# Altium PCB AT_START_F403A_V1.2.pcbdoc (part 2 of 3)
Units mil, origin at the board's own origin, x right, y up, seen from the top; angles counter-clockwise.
Board outline 5262.73 x 3522.74 mil, 2 copper layers (Top Layer, Bottom Layer); 135 components, 162 nets, 647 pads, 293 vias.
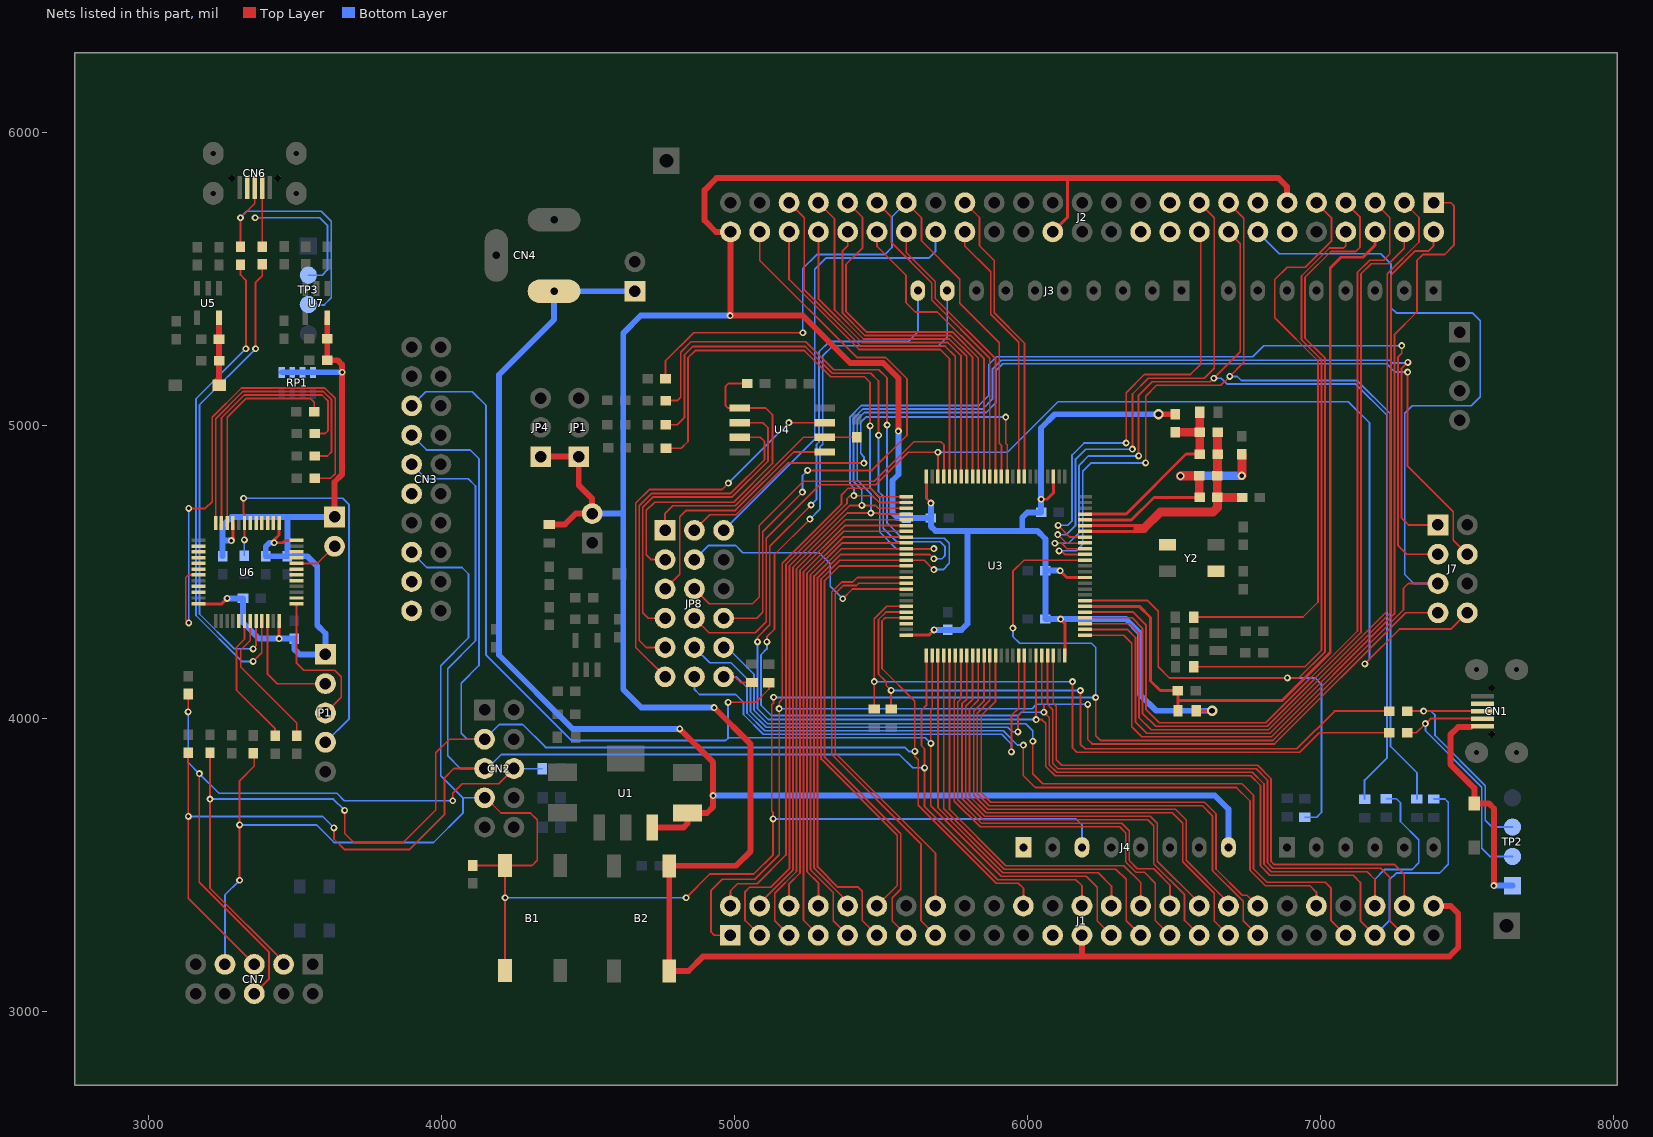
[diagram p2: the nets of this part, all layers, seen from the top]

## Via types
v1: diameter 23.62, hole 11.81, Top Layer to Bottom Layer, 286 vias
v2: diameter 28, hole 16, Top Layer to Bottom Layer, 3 vias
v3: diameter 35, hole 20, Top Layer to Bottom Layer, 2 vias
v4: diameter 29.53, hole 13.78, Top Layer to Bottom Layer, 1 vias
v5: diameter 31.5, hole 15.75, Top Layer to Bottom Layer, 1 vias

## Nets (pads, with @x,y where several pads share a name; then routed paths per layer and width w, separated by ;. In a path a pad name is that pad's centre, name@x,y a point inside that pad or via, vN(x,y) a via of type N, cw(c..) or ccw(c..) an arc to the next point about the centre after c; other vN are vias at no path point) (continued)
JDI: CN3.5 J1.27 R36.2 U3.77 | length 4479.2
  Top Layer w6: v1(4978.99,4056.68) 5072.99,4056.68 5118.45,4102.13 R36.2@5118.45,4123.59 ; U3.77@5675.49,4216.94 5675.49,4033.06 5670.99,4028.55 v1(5670.99,3916.74) 5670.99,3703.83 5911.73,3463.09 6201.64,3463.09 6238.99,3425.74 6238.99,3310.15 J1.27@6287.12,3262.02
  Bottom Layer w6: CN3.5@3898.99,5068.74 3946.99,5116.74 4105.99,5116.74 4152.99,5069.74 4152.99,4217.71 4443.96,3926.74 4971.37,3926.74 4978.99,3934.36 4978.99,3935.06 ; v1(4978.99,4056.68) 4978.99,3935.06 ; v1(5670.99,3916.74) 5651.85,3935.88 4979.82,3935.88 4978.99,3935.06
JTCK: CN2.5 CN3.9 CN7.5 J1.26 R41.1 U3.76 | length 6221.8
  Top Layer w6: R41.1@3136.85,3884.34 v1(3136.85,3667.34) 3136.85,3387.34 CN7.5@3361.85,3162.34 ; v1(3633.85,3628.34) 3633.85,3590.34 3670.13,3554.06 3891.37,3554.06 4011.37,3674.06 4011.37,3799.54 4042.57,3830.74 CN2.5@4147.99,3830.74 ; v1@5648.99,3833.06 5648.99,3701.78 5899.68,3451.09 6165.99,3451.09 6187.12,3429.96 J1.26@6187.12,3362.02 ; v1(5649.37,3833.06) 5649.37,3898.06 5638.87,3908.56 5638.87,4029.11 5655.81,4046.06 U3.76@5655.81,4216.94
  Bottom Layer w6: v1(3136.85,3667.34) 3594.85,3667.34 v1(3633.85,3628.34) ; CN3.9@3898.99,4868.74 3947.99,4819.74 4091.99,4819.74 4116.99,4794.74 4116.99,4266.74 4021.99,4171.74 4021.99,3873.74 4064.99,3830.74 CN2.5@4147.99,3830.74 4156.37,3830.74 4204.37,3878.74 4234.37,3878.74 5506.05,3878.74 5563.37,3878.74 5609.05,3833.06 v1(5649.37,3833.06)
JTMS: CN2.3 CN3.7 CN7.3 J1.22 R44.1 U3.72 | length 6275.2
  Top Layer w6: R44.1@3210.85,3884.34 3210.85,3422.55 3461.85,3171.55 CN7.3@3461.85,3162.34 ; v1(3670.37,3688.06) 3670.37,3608.95 3701.26,3578.06 3870.37,3578.06 3981.37,3689.06 3981.37,3884.06 4028.05,3930.74 CN2.3@4147.99,3930.74 ; U3.72@5586.91,4344.89 5515.06,4344.89 5504.37,4334.2 5504.37,4172.06 5616.37,4060.06 v1(5616.37,3889.06) 5616.37,3872.87 5628.18,3861.06 5628.18,3705.62 5894.71,3439.09 5969.64,3439.09 5987.12,3421.61 J1.22@5987.12,3362.02
  Bottom Layer w6: v1(3210.76,3726.42) 3632,3726.42 v1(3670.37,3688.06) ; CN3.7@3898.99,4968.74 3949.99,4917.74 4098.99,4917.74 4128.99,4887.74 4128.99,4182.74 4067.99,4121.74 4067.99,3951.74 4088.99,3930.74 CN2.3@4147.99,3930.74 4198.31,3981.06 4277.68,3981.06 4355.99,3902.74 5582.37,3902.74 5596.05,3889.06 v1(5616.37,3889.06)
LD1: LD1.2 U6.10 | length 723.1
  Top Layer w6: U6.10@3269.42,4668.34 3269.42,5029.75 3333.01,5093.34 3554.85,5093.34 3566.85,5081.34 LD1.2@3566.85,5048.34
LD2: LD2.2 U6.11 | length 914.2
  Top Layer w6: U6.11@3249.74,4668.34 3249.74,5027.04 3328.04,5105.34 3592.85,5105.34 3613.85,5084.34 3613.85,4984.34 3603.75,4974.24 LD2.2@3567.81,4974.24
LD3: LD3.2 U6.12 | length 1043.7
  Top Layer w6: U6.12@3230.05,4668.34 3230.05,5024.32 3323.07,5117.34 3597.82,5117.34 3625.85,5089.31 3625.85,4911.34 3611.85,4897.34 LD3.2@3567.85,4897.34
LD4: LD4.2 U6.19 | length 1781.6
  Top Layer w6: v1(3138.37,4328.06) 3128.37,4338.06 3128.37,4482.69 3136.86,4491.17 U6.19@3171,4491.17 ; v1(3138.37,4718.34) 3194.85,4718.34 3218.05,4741.55 3218.05,5029.29 3318.1,5129.34 3602.79,5129.34 3637.85,5094.28 3637.85,4837.34 3621.85,4821.34 LD4.2@3567.81,4821.34
  Bottom Layer w6: v1(3138.37,4328.06) v1(3138.37,4718.34)
M-ATLK_RX: R48.2 U6.31 | length 483.9
  Top Layer w6: U6.31@3348.16,4333.69 3348.16,4267.66 3315.85,4235.34 3315.85,4177.06 3506.85,3986.06 R48.2@3506.85,3942.34
M-ATLK_TX: R47.2 U6.30 | length 457.3
  Top Layer w6: U6.30@3328.48,4333.69 3328.48,4271.97 3301.11,4244.6 3301.11,4097.96 3432.85,3966.22 R47.2@3432.85,3942.34
M-BOOT0: J9.2 U6.44 | length 154.6
  Top Layer w6: U6.44@3505.64,4530.55 3577.05,4530.55 J9.2@3635.85,4589.34
M-NRST: C22.1 P1.4 U6.7 | length 1411.3
  Top Layer w6: v1(3325.37,4753.06) 3325.37,4702.33 3328.48,4699.22 U6.7@3328.48,4668.54 3328.48,4611.78 v1(3328.04,4611.34)
  Bottom Layer w6: v1(3325.37,4753.06) 3663.81,4753.06 3685.44,4731.43 3685.44,4000.93 P1.4@3604.85,3920.34 ; C22.1@3327.35,4556.67 v1@3327.35,4611.34
M-SWCLK: P1.3 U6.37 | length 520.5
  Top Layer w6: U6.37@3505.64,4392.75 3505.64,4191.24 3530.55,4166.34 3636.85,4166.34 3658.85,4144.34 3658.85,4074.34 P1.3@3604.85,4020.34
M-SWDIO: P1.2 U6.34 | length 392.1
  Top Layer w6: U6.34@3407.22,4333.89 3407.22,4152.97 3439.85,4120.34 P1.2@3604.85,4120.34
M-USB_DM: R38.2 U6.32 | length 1612.4
  Top Layer w6: v1(3357.85,4239.34) 3367.85,4249.34 U6.32@3367.85,4333.69 ; v1(3366.43,5263.34) 3366.43,5489.92 3388.85,5512.34 R38.2@3388.85,5551.19
  Bottom Layer w6: v1(3357.85,4239.34) 3293.56,4239.34 3174.85,4358.06 3174.85,5071.76 v1(3366.43,5263.34)
M-USB_DP: R37.2 U6.33 | length 1685.3
  Top Layer w6: R37.2@3314.85,5550.23 3314.85,5515.34 3333.43,5496.76 v1(3333.43,5263.34) ; v1(3357.85,4196.34) 3387.53,4226.03 U6.33@3387.53,4333.89
  Bottom Layer w6: v1(3333.43,5263.34) 3162.85,5092.76 3162.85,4353.08 3319.59,4196.34 v1(3357.85,4196.34)
NRST: B1.1 CB1.1 CN2.7 CN3.15 CN7.7 J2.14 J4.3 J7.5 R46.1 U3.14 | length 12191.6
  Top Layer w6: v1(3311.85,3449.34) v1(3311.85,3638.34) 3311.85,3789.34 3361.85,3839.34 3361.85,3879.34 R46.1@3358.85,3882.34 ; CB1.1@4106.99,3499.74 B1.1@4217.99,3499.74 ; CN2.7@4147.99,3730.74 4152.37,3730.74 4204.05,3679.06 4304.37,3679.06 4327.37,3656.06 4327.37,3517.06 4310.05,3499.74 B1.1@4217.99,3499.74 ; B1.1@4217.99,3140.74 v1(4217.99,3389.74) B1.1@4217.99,3499.74 ; v1(4835.99,3389.74) 4916.99,3470.74 5066.75,3470.74 5132.56,3536.55 v1(5132.56,3658.55) 5132.56,3680.06 5128.21,3684.4 5128.21,4048.9 5134.37,4055.06 v1(5134.37,4074.06) ; v1(5951.09,4309.74) 5951.09,4503.83 5988.99,4541.74 U3.14@6206.99,4541.74 ; v1(6233.37,4073.06) 6233.37,3942.06 6248.68,3926.74 6838.96,3926.74 ; 6838.67,3927.03 7274.69,4363.04 7283.96,4372.32 7283.96,4445.71 7300.42,4462.17 J7.5@7401.7,4462.17
  Bottom Layer w6: CN7.7@3261.85,3162.34 3261.85,3399.34 v1(3311.85,3449.34) ; v1(3311.85,3638.34) 3574.11,3638.34 3634.4,3578.06 3973.4,3578.06 4073.83,3678.49 4073.83,3730.74 ; CN3.15@3898.99,4568.74 3950.99,4516.74 4070.99,4516.74 4092.99,4494.74 4092.99,4276.68 3997.99,4181.68 3997.99,3806.58 4073.83,3730.74 ; CN2.7@4147.99,3730.74 4073.83,3730.74 ; v1(4217.99,3389.74) v1(4835.99,3389.74) ; v1(5132.56,3658.55) 6166.18,3658.55 6186.69,3638.04 J4.3@6186.69,3561.59 ; v1(5134.37,4074.06) 5135.37,4073.06 v1(6233.37,4073.06) 6233.37,4243.74 6219.05,4258.06 5974.37,4258.06 5951.09,4281.34 v1(5951.09,4309.74) ; J2.14@6786.7,5661.59 6860.55,5587.74 7206.99,5587.74 7240.99,5553.74 7240.99,5403.74 7258.99,5385.74 7518.99,5385.74 7545.99,5358.74 7545.99,5099.74 7514.99,5068.74 7313.84,5068.74 7287.99,5042.89 7287.99,4492.74 7318.57,4462.17 J7.5@7401.7,4462.17
PA8: JP8.5 U3.67 | length 876.6
  Top Layer w6: v1(5370.31,4410.06) 5403.57,4443.31 U3.67@5586.91,4443.31
  Bottom Layer w6: JP8.5@4863.99,4543.74 4912.31,4592.06 5004.37,4592.06 5029.37,4567.06 5289.37,4567.06 5327.37,4529.06 5327.37,4453 v1(5370.31,4410.06)
PA11: R22.2 R29.1 U3.70 | length 2452.6
  Top Layer w6: R29.1@5477.85,4033.69 v1(5477.85,4127.22) 5477.85,4341.62 5520.49,4384.26 U3.70@5586.91,4384.26 ; v1(6154.37,4127.06) 6154.37,3900.99 6169.31,3886.05 6930.51,3886.06 6996.99,3952.54 R22.2@7236.03,3952.54
  Bottom Layer w6: v1@5477.85,4127.06 v1(6154.37,4127.06)
PA12: R20.2 R30.1 U3.71 | length 2371.8
  Top Layer w6: R30.1@5535.15,4033.94 v1(5535.15,4097.22) 5518.37,4114.01 5518.37,4127.11 5492.37,4153.11 5492.37,4339.17 5517.78,4364.57 U3.71@5586.91,4364.57 ; v1(6181.37,4097.06) 6181.37,3914.06 6197.37,3898.06 6920.31,3898.06 7048.99,4026.74 R20.2@7235.99,4026.74
  Bottom Layer w6: v1@5535.15,4097.06 v1(6181.37,4097.06)
PB1: JP8.2 U3.36 | length 1529.1
  Top Layer w6: JP8.2@4863.99,4643.74 4916.99,4696.74 5005.9,4696.74 5182.22,4873.06 v1(5442.37,4873.06) v1@5446.37,4873.06 ; v1(5926.69,5030.06) 5926.69,4940.04 5931.4,4935.33 U3.36@5931.4,4827.17
  Bottom Layer w6: v1(5442.37,4873.06) 5442.37,4895.06 5431.37,4906.06 5431.37,5013.06 5448.37,5030.06 v1(5926.69,5030.06)
PB1_E: J2.36 JP8.3 | length 1524
  Bottom Layer w6: JP8.3@4963.99,4643.74 5274.37,4954.12 5274.37,5535.06 5312.05,5572.74 5663.99,5572.74 5687.12,5595.87 J2.36@5687.12,5662.02
PB2: J2.37 R25.1 U3.37 | length 2364.7
  Top Layer w6: R25.1@4765.33,5161.58 4765.33,5222.01 4861.37,5318.06 v1(5233.99,5318.06) ; J2.37@5587.12,5762.02 5638.99,5710.14 5638.99,5631.84 5769.99,5500.84 5769.99,5418.77 5904.37,5284.39 5904.37,4940.36 5911.72,4933.02 U3.37@5911.72,4827.17
  Bottom Layer w6: v1(5233.99,5318.06) 5233.99,5537.36 5281.37,5584.74 5513.99,5584.74 5537.99,5608.74 5537.99,5712.89 J2.37@5587.12,5762.02
PB6: JP8.17 U3.92 | length 1592.7
  Top Layer w6: v1(5945.99,3887.74) 5945.99,4011.74 5970.77,4036.52 U3.92@5970.77,4216.94
  Bottom Layer w6: JP8.17@4863.99,4143.74 4863.99,4100.74 4881.37,4083.36 5004.68,4083.36 5031.37,4056.68 5031.37,4015.17 5098.66,3947.88 5912.57,3947.88 5945.99,3914.46 v1(5945.99,3887.74)
PB6_E: J1.42 JP8.18 R35.2 | length 2729.6
  Top Layer w6: JP8.18@4963.99,4143.74 5001.86,4143.74 5021.32,4124.27 5060.33,4124.27 R35.2@5060.55,4124.05 ; v1(5986.69,3910.74) 5986.69,3807.04 6027.99,3765.74 6713.99,3765.74 6759.99,3719.74 6759.99,3483.92 6813.17,3430.74 6964.99,3430.74 6986.7,3409.04 J1.42@6986.7,3361.59
  Bottom Layer w6: JP8.18@4963.99,4143.74 5006.99,4143.74 5043.37,4107.36 5043.37,4020.14 5103.63,3959.88 5917.54,3959.88 5966.68,3910.74 v1(5986.69,3910.74) ; J1.42@6986.7,3361.59 J1.42@6987.03,3361.93
PB7: JP8.14 U3.93 | length 1552.1
  Top Layer w6: v1(5968.02,3956.06) 5968.02,4009.77 5990.46,4032.2 U3.93@5990.46,4216.94
  Bottom Layer w6: JP8.14@4863.99,4243.74 4915.99,4191.74 4988.99,4191.74 5055.37,4125.36 5055.37,4025.11 5108.6,3971.88 5123.37,3971.88 5932.88,3971.88 5948.71,3956.06 v1(5968.02,3956.06)
PB7_E: J1.43 JP8.15 | length 2899.3
  Top Layer w6: v1(6018.99,3923.74) 6018.99,3812.74 6052.99,3778.74 6732.99,3778.74 6771.99,3739.74 6771.99,3488.89 6818.14,3442.74 7016.99,3442.74 7036.99,3422.74 7036.99,3311.3 J1.43@7086.7,3261.59
  Bottom Layer w6: JP8.15@4963.99,4243.74 4975.96,4243.74 5067.37,4152.33 5067.37,4030.08 5113.57,3983.88 5676.37,3983.88 5994.54,3983.88 6018.99,3959.43 v1(6018.99,3923.74)
PB8: J1.45 J3.10 R33.1 U3.95 | length 5480.1
  Top Layer w6: v1(5079.37,4263.06) 5079.37,4279.06 5121.37,4321.06 5121.37,4589.06 v1(5262.37,4730.06) ; v1@6029.83,3997.74 U3.95@6029.83,4216.94 ; v1(6029.99,3997.74) 6049.99,3997.74 6062.99,3984.74 6062.99,3837.8 6095.05,3805.74 6763.02,3805.74 6795.99,3772.77 6795.99,3498.83 6828.08,3466.74 7111.99,3466.74 7136.99,3441.74 7136.99,3311.3 J1.45@7186.7,3261.59
  Bottom Layer w6: v1(5079.37,4263.06) 5079.37,4035.06 5116.68,3997.74 5163.37,3997.74 6002.99,3997.74 v1(6029.99,3997.74) ; v1(5262.37,4730.06) 5280.37,4748.06 5280.37,4936.06 5289.37,4945.06 5289.37,5253.06 5324.05,5287.74 5593.99,5287.74 5626.69,5320.44 J3.10@5626.69,5461.59 ; J1.45@7186.7,3261.59 7235.99,3310.89 7235.99,3450.74 7258.99,3473.74 7406.99,3473.74 7436.99,3503.74 7436.99,3715.37 7425.69,3726.67 R33.1@7386.97,3726.67
PB9: J1.46 J3.9 R31.1 U3.96 | length 5332.3
  Top Layer w6: v1(5111.37,4263.06) 5111.37,4280.06 5137.37,4306.06 5137.37,4561.06 v1(5258.37,4682.06) ; U3.96@6049.51,4216.94 6049.51,4052.74 6056.99,4045.26 v1(6056.99,4022.74) 6074.99,4004.74 6074.99,3842.77 6100.02,3817.74 6767.99,3817.74 6807.99,3777.74 6807.99,3503.8 6833.05,3478.74 7159.99,3478.74 7186.7,3452.04 J1.46@7186.7,3361.59
  Bottom Layer w6: v1(5111.37,4263.06) 5111.37,4239.06 5091.37,4219.06 5091.37,4047.06 5126.83,4011.6 5967.37,4011.6 5978.51,4022.74 v1(6056.99,4022.74) ; v1(5258.37,4682.06) 5292.37,4716.06 5292.37,4928.06 5302.37,4938.06 5302.37,5239.06 5337.05,5273.74 5696.99,5273.74 5726.69,5303.44 J3.9@5726.69,5461.59 ; J1.46@7186.7,3361.59 7186.7,3453.44 7218.99,3485.74 7312.99,3485.74 7335.99,3508.74 7335.99,3587.74 7273.99,3649.74 7273.99,3713.74 7260.1,3727.63 R31.1@7224.87,3727.63
PB10: JP8.8 U3.47 | length 1348.3
  Top Layer w6: JP8.8@4863.99,4443.74 4914.68,4393.06 5062.37,4393.06 5085.37,4416.06 5085.37,4660.06 5236.37,4811.06 5478.37,4811.06 5613.37,4946.06 5705.37,4946.06 5715.99,4935.43 5715.99,4838.14 U3.47@5714.86,4837.02
PB11: J7.8 JP8.11 U3.48 | length 4182.8
  Top Layer w6: JP8.11@4863.99,4343.74 4913.68,4294.06 5071.37,4294.06 5109.37,4332.06 5109.37,4616.43 5291.99,4799.06 5483.34,4799.06 5594.34,4910.06 v1(5695.18,4910.06) U3.48@5695.18,4827.17 ; v1(7151.99,4187.74) 7270.43,4306.18 7270.43,4307.3 7446.83,4307.3 J7.8@7501.7,4362.17
  Bottom Layer w6: v1(5695.18,4910.06) 5932.37,4910.06 6105.05,5082.74 6121.37,5082.74 7095.99,5082.74 7167.99,5010.74 7167.99,4203.74 v1(7151.99,4187.74)
PB11_E: J2.48 JP8.12 | length 2037.7
  Top Layer w6: JP8.12@4963.99,4343.74 5077.05,4343.74 5097.37,4364.06 5097.37,4638.32 v1(5232.79,4773.74) ; J2.48@5087.12,5662.02 5087.12,5564.64 5418.02,5233.74 5516.24,5233.74 5589.37,5160.61 5589.37,4967.62 5469.8,4848.06 v1(5250.37,4848.06)
  Bottom Layer w6: v1(5232.79,4773.74) 5232.79,4830.47 v1(5250.37,4848.06)
PB12: J1.1 J7.7 U3.51 | length 4620.3
  Top Layer w6: J1.1@4987.12,3262.02 4931.72,3262.02 4920.99,3272.74 4920.99,3415.09 4958.64,3452.74 5070.05,3452.74 5153.37,3536.06 v1(5153.37,4035.06) 5153.37,4057.43 5163.99,4068.06 5163.99,4531.75 5366.37,4734.13 5366.37,4765.34 5388.08,4787.06 5466.37,4787.06 5495.15,4758.28 U3.51@5586.91,4758.28 ; v1(6206.37,4049.74) 6206.37,3929.74 6221.37,3914.74 6254.37,3914.74 6843.93,3914.74 7291.36,4362.17 J7.7@7401.7,4362.17
  Bottom Layer w6: v1(5153.37,4035.06) 6016.37,4035.06 6031.05,4049.74 v1(6206.37,4049.74)
PB13: J1.2 J7.3 U3.52 | length 4968.1
  Top Layer w6: J1.2@4987.12,3362.02 4987.12,3413.87 5010.99,3437.74 5078.63,3437.74 5176.37,3535.48 5176.37,4527.16 5384.58,4735.37 5384.58,4750.74 5395.89,4762.06 v1(5408.37,4762.06) 5471.05,4762.06 5494.52,4738.59 U3.52@5586.91,4738.59 ; U3.52@5574.92,4740.74 U3.52@5577.07,4738.59 ; v1(7277.99,5273.74) 7277.99,5247.74 7264.99,5234.74 7264.99,4592.8 7295.63,4562.17 J7.3@7401.7,4562.17
  Bottom Layer w6: v1(5408.37,4762.06) 5408.37,4788.06 5395.37,4801.06 5395.37,5031.08 5434.02,5069.74 5834.99,5069.74 5868.99,5103.74 5868.99,5209.74 5894.99,5235.74 6768.99,5235.74 6806.99,5273.74 v1(7277.99,5273.74)
PB14: J1.3 J7.1 U3.53 | length 4895.3
  Top Layer w6: J1.3@5087.12,3262.02 5036.99,3312.15 5036.99,3410.68 5052.05,3425.74 5125.05,3425.74 5187.99,3488.68 ; 5188.37,3489.06 5188.37,4522.19 5394.92,4728.74 5481.7,4728.74 5491.53,4718.91 U3.53@5586.91,4718.91 ; v1(7298.99,5216.74) 7276.99,5194.74 7276.99,4686.12 7300.94,4662.17 J7.1@7401.7,4662.17
  Bottom Layer w6: v1(5435.37,4729.06) 5435.37,4782.07 5407.37,4810.07 5407.37,5026.11 5438.99,5057.74 5847.99,5057.74 5880.99,5090.74 5880.99,5193.71 5911.02,5223.74 7237.18,5223.74 7245.99,5214.93 7297.18,5214.93 v1(7298.99,5216.74)
PB15: J1.4 J7.4 U3.54 | length 4743.9
  Top Layer w6: J1.4@5087.12,3362.02 5087.12,3370.84 5199.99,3483.71 ; 5200.37,3484.09 5200.37,4517.22 5385.89,4702.74 v1(5466.37,4702.74) 5490.47,4702.74 5493.99,4699.22 U3.54@5586.91,4699.22 ; v1(7297.99,5183.74) 7297.99,4862.74 7453.99,4706.74 7453.99,4609.87 J7.4@7501.7,4562.17
  Bottom Layer w6: v1(5466.37,4702.74) 5466.37,4768.36 5419.37,4815.36 5419.37,5021.14 5443.97,5045.74 5859.99,5045.74 5892.99,5078.74 5892.99,5188.74 5915.99,5211.74 7226.99,5211.74 7254.99,5183.74 v1(7297.99,5183.74)
PC0: J2.15 R34.1 U3.15 | length 3798.7
  Top Layer w6: v1(6108.99,4573.74) 6115.42,4573.74 6127.74,4561.43 U3.15@6206.99,4561.43 ; v1(6403.99,4873.74) 6403.99,5101.43 6440.99,5138.43 6660.68,5138.43 v1(6690.99,5168.74) 6738.99,5216.74 6738.99,5709.29 J2.15@6686.7,5761.59
  Bottom Layer w6: v1(6108.99,4573.74) 6166.99,4573.74 6188.99,4595.74 6188.99,4844.74 6217.99,4873.74 v1(6403.99,4873.74) ; v1(6690.99,5168.74) 6716.99,5168.74 6730.99,5154.74 7125.81,5154.74 7239.99,5040.56 7239.99,3905.74 7330.04,3815.69 R34.1@7330.04,3726.44
PC1: J2.16 R32.1 U3.16 | length 3690.9
  Top Layer w6: v1(6093.99,4599.58) 6117.15,4599.58 6135.62,4581.11 U3.16@6206.99,4581.11 ; v1(6379.99,4897.74) 6379.99,5104.43 6425.99,5150.43 6624.68,5150.43 v1(6636.99,5162.74) 6726.99,5252.74 6726.99,5621.29 J2.16@6686.7,5661.59
  Bottom Layer w6: v1(6093.99,4599.58) 6140.83,4599.58 6176.99,4635.74 6176.99,4865.74 6208.99,4897.74 v1(6379.99,4897.74) ; v1(6636.99,5162.74) 6661.99,5162.74 6681.99,5142.74 7120.84,5142.74 7227.99,5035.59 7227.99,3868.07 7151.2,3791.27 R32.1@7151.2,3725.7
PC2: J2.17 U3.17 | length 1713
  Top Layer w6: v1(6103.99,4628.74) 6104.96,4628.74 6133.96,4599.74 6205.94,4599.74 U3.17@6206.99,4600.8 ; v1(6358.99,4920.74) 6358.99,5108.74 6412.99,5162.74 6603.5,5162.74 6637.99,5197.23 6637.99,5710.29 J2.17@6586.7,5761.59
  Bottom Layer w6: v1(6103.99,4628.74) 6132.99,4628.74 6164.99,4660.74 6164.99,4886.74 6198.99,4920.74 v1(6358.99,4920.74)
PC3: J2.18 U3.18 | length 1518.9
  Top Layer w6: v1(6104.99,4660.74) 6145.25,4620.48 U3.18@6206.99,4620.48 ; v1(6337.47,4941.74) 6337.47,5113.32 6399.99,5175.84 6557.12,5175.84 6591.99,5210.71 6591.99,5656.29 J2.18@6586.7,5661.59
  Bottom Layer w6: v1(6104.99,4660.74) 6137.99,4660.74 6152.99,4675.74 6152.99,4900.74 6193.99,4941.74 v1(6337.47,4941.74)
PC4: J2.33 U3.33 | length 1018.8
  Top Layer w6: J2.33@5786.7,5761.59 5836.99,5711.29 5836.99,5614.74 5887.12,5564.61 5887.12,5385.61 5990.46,5282.28 U3.33@5990.46,4827.17
PC5: J2.34 U3.34 | length 910.7
  Top Layer w6: J2.34@5786.7,5661.59 5786.7,5614.04 5875.12,5525.61 5875.12,5380.64 5970.77,5284.99 U3.34@5970.77,4827.17
PC6: J1.13 U3.63 | length 1649.4
  Top Layer w6: U3.63@5586.91,4522.06 5357.94,4522.06 5308.37,4472.49 5308.37,3868.6 5568.4,3608.57 5568.4,3418.67 5538.99,3389.26 5538.99,3310.15 J1.13@5587.12,3262.02
PC8: J1.15 U3.65 | length 1593.1
  Top Layer w6: U3.65@5586.91,4482.69 5419.51,4482.69 5404.14,4467.31 5366.66,4467.31 5332.37,4433.03 5332.37,3878.54 5636.99,3573.92 5636.99,3312.15 J1.15@5687.12,3262.02
PC9: J1.16 U3.66 | length 1465
  Top Layer w6: U3.66@5586.91,4463 5425.05,4463 5417.37,4455.31 5371.63,4455.31 5344.37,4428.06 5344.37,3883.51 5687.12,3540.76 J1.16@5687.12,3362.02
PC10: J1.28 U3.78 | length 1290.5
  Top Layer w6: U3.78@5695.18,4216.94 5695.18,3696.61 5916.7,3475.09 6241.64,3475.09 6287.12,3429.61 J1.28@6287.12,3362.02
PC11: J1.29 U3.79 | length 1456.5
  Top Layer w6: U3.79@5714.86,4216.94 5714.86,3693.9 5921.67,3487.09 6302.64,3487.09 6337.47,3452.26 6337.47,3311.66 J1.29@6387.12,3262.02
PC12: J1.30 U3.80 | length 1361.3
  Top Layer w6: U3.80@5734.55,4216.94 5734.55,3691.18 5926.64,3499.09 6329.64,3499.09 6387.12,3441.61 J1.30@6387.12,3362.02
PC13: J2.7 R21.2 U3.7 | length 3411.6
  Top Layer w6: U3.7@6197.15,4403.94 6410.79,4403.94 6446.99,4367.74 6446.99,4177.74 6484.99,4139.74 v1(6887.99,4139.74) 6926.93,4139.74 7016.37,4229.18 7016.37,5231.3 6947.99,5299.68 6947.99,5506.8 7036.45,5595.25 7120.51,5595.25 7135.99,5610.74 7135.99,5712.29 J2.7@7086.7,5761.59
  Bottom Layer w6: v1(6887.99,4139.74) 6982.99,4139.74 7003.99,4118.74 7003.99,3680.74 6987.99,3664.74 R21.2@6946.99,3664.74
PC14: J2.8 R5.2 | length 2005.6
  Top Layer w6: R5.2@6568.47,4177.71 6947.94,4177.71 7004.37,4234.15 7004.37,5226.33 6935.99,5294.71 6935.99,5511.77 7031.48,5607.25 7079.51,5607.25 7086.7,5614.44 J2.8@7086.7,5661.59
PC15: J2.9 R8.2 | length 2006.7
  Top Layer w6: R8.2@6567.99,4347.74 6941.05,4347.74 6992.37,4399.06 6992.37,5221.36 6844.99,5368.74 6844.99,5499.74 6886.99,5541.74 6948.99,5541.74 7037.99,5630.74 7037.99,5710.29 J2.9@6986.7,5761.59
PD0: J1.31 U3.81 | length 1557
  Top Layer w6: U3.81@5754.23,4216.94 5754.23,4068.98 5750.99,4065.74 5750.99,3719.65 5838.9,3631.74 6314.99,3631.74 6335.99,3610.74 6335.99,3511.77 6371.02,3476.74 6399.99,3476.74 6436.99,3439.74 6436.99,3312.15 J1.31@6487.12,3262.02
PD1: J1.32 U3.82 | length 1471.7
  Top Layer w6: U3.82@5773.92,4216.94 5773.92,4068.67 5762.99,4057.74 5762.99,3724.62 5843.87,3643.74 6321.99,3643.74 6347.99,3617.74 6347.99,3516.74 6375.99,3488.74 6431.02,3488.74 6487.12,3432.64 J1.32@6487.12,3362.02
PD2: J1.33 U3.83 | length 1625.9
  Top Layer w6: U3.83@5793.61,4216.94 5793.6,4067.76 5776.99,4051.15 5776.99,3728.89 5850.14,3655.74 6410.99,3655.74 6431.99,3634.74 6431.99,3504.74 6536.99,3399.74 6536.99,3312.15 J1.33@6587.12,3262.02
PD3: J1.34 U3.84 | length 1525.7
  Top Layer w6: U3.84@5813.29,4216.94 5813.29,4067.04 5789.99,4043.74 5789.99,3732.86 5855.11,3667.74 6419.99,3667.74 6443.99,3643.74 6443.99,3514.71 6587.12,3371.58 J1.34@6587.12,3362.02
PD4: J1.35 U3.85 | length 1705.7
  Top Layer w6: U3.85@5832.98,4216.94 5832.98,4063.72 5802.99,4033.74 5802.99,3736.83 5860.08,3679.74 6494.99,3679.74 6530.62,3644.11 6530.62,3512.11 6637.99,3404.74 6637.99,3310.3 J1.35@6686.7,3261.59
PD5: J1.36 U3.86 | length 1605.8
  Top Layer w6: U3.86@5852.66,4216.94 5852.66,4062.41 5816.99,4026.74 5816.99,3739.8 5865.05,3691.74 6505.99,3691.74 6542.62,3655.11 6542.62,3517.09 6686.7,3373.01 J1.36@6686.7,3361.59
PD6: J1.37 U3.87 | length 1796.4
  Top Layer w6: U3.87@5872.35,4216.94 5872.35,4063.09 5828.99,4019.74 5828.99,3744.77 5870.02,3703.74 6597.99,3703.74 6631.99,3669.74 6631.99,3482.77 6736.99,3377.77 6736.99,3311.3 J1.37@6786.7,3261.59
PD7: J1.38 U3.88 | length 1703.9
  Top Layer w6: U3.88@5892.03,4216.94 5892.03,4060.78 5842.99,4011.74 5842.99,3747.74 5874.99,3715.74 6604.99,3715.74 6643.99,3676.74 6643.99,3487.74 6733.21,3398.52 6749.77,3398.52 J1.38@6786.7,3361.59
PD8: J1.5 U3.55 | length 1745.2
  Top Layer w6: J1.5@5187.12,3262.02 5137.99,3311.15 5137.99,3404.74 5212.37,3479.12 5212.37,4512.25 5379.65,4679.54 U3.55@5586.91,4679.54
PD9: J1.6 U3.56 | length 1586.4
  Top Layer w6: J1.6@5187.12,3362.02 5187.12,3436.81 5224.37,3474.06 5224.37,4507.28 5376.94,4659.85 U3.56@5586.91,4659.85
PD10: J1.7 U3.57 | length 1669
  Top Layer w6: J1.7@5287.12,3262.02 5236.37,3312.77 5236.37,4502.31 5374.23,4640.17 U3.57@5586.91,4640.17
PD11: J1.8 U3.58 | length 1541.6
  Top Layer w6: J1.8@5287.57,3362.46 5287.12,3362.02 5287.12,3440.3 5248.37,3479.06 5248.37,4497.34 5371.51,4620.48 U3.58@5586.91,4620.48
PD12: J1.9 U3.59 | length 1654.3
  Top Layer w6: J1.9@5387.12,3262.02 5337.99,3311.15 5337.99,3407.43 5260.37,3485.06 5260.37,4492.37 5368.8,4600.8 U3.59@5586.91,4600.8
PD13: J1.10 LED2.2 U3.60 | length 3399.7
  Top Layer w6: LED2.2@4766.99,4923.37 4818.62,4923.37 4841.99,4946.74 4841.99,5232.06 4866.99,5257.06 5239.76,5257.06 5329.08,5167.74 5444.68,5167.74 5463.37,5149.06 v1(5463.37,5000.06) ; J1.10@5387.12,3362.02 5387.12,3375.3 5272.37,3490.06 5272.37,4487.4 5366.08,4581.11 U3.60@5586.91,4581.11 v1(5680.99,4581.11)
  Bottom Layer w6: v1(5463.37,5000.06) 5463.37,4788.33 5496.6,4755.1 5496.6,4637.88 5553.37,4581.11 v1(5680.99,4581.11)
PD14: J1.11 LED3.2 U3.61 | length 3610.1
  Top Layer w6: LED3.2@4766.38,5004.15 4805.74,5004.15 4829.99,5028.41 4829.99,5242.06 4858.99,5271.06 5242.73,5271.06 5334.05,5179.74 5465.81,5179.74 5492.37,5153.18 v1(5492.37,4968.06) ; J1.11@5487.12,3262.02 5436.99,3312.15 5436.99,3411.74 5422.68,3426.06 5353.34,3426.06 5284.37,3495.03 5284.37,4482.43 5363.37,4561.43 U3.61@5586.91,4561.43 5666.31,4561.43 v1(5680.99,4546.74)
  Bottom Layer w6: v1(5492.37,4968.06) 5492.37,4776.3 5508.6,4760.07 5508.6,4651.13 5554.99,4604.74 5702.99,4604.74 5718.99,4588.74 5718.99,4556.74 5708.99,4546.74 v1(5680.99,4546.74)
PD15: J1.12 LED4.2 U3.62 | length 3522.5
  Top Layer w6: LED4.2@4765.99,5086.37 4805.96,5086.37 4817.33,5097.74 4817.33,5252.06 4852.33,5287.06 5243.71,5287.06 5339.02,5191.74 5493.37,5191.74 5521.37,5163.74 v1(5521.37,5003.06) ; J1.12@5487.12,3362.02 5556.4,3431.29 5556.4,3603.6 5296.37,3863.63 5296.37,4477.46 5360.65,4541.74 U3.62@5586.91,4541.74 5648.02,4541.74 5680.02,4509.74 v1(5680.99,4509.74)
  Bottom Layer w6: v1(5521.37,5003.06) 5521.37,4669.06 5573.68,4616.74 5716.14,4616.74 5733.99,4598.89 5733.99,4530.74 5712.99,4509.74 v1(5680.99,4509.74)
PE0: J1.47 U3.97 | length 2071.2
  Top Layer w6: U3.97@6069.2,4216.94 6069.2,4049.74 6086.99,4031.94 6086.99,3847.74 6104.99,3829.74 6781.02,3829.74 6819.99,3790.77 6819.99,3508.77 6838.02,3490.74 7205.99,3490.74 7236.99,3459.74 7236.99,3311.3 J1.47@7286.7,3261.59
PE1: J1.48 U3.98 | length 1983.6
  Top Layer w6: U3.98@6088.88,4216.94 6088.88,4053.74 6098.99,4043.63 6098.99,3860.74 6117.99,3841.74 6785.99,3841.74 6831.99,3795.74 6831.99,3513.74 6842.99,3502.74 7253.99,3502.74 7286.7,3470.04 J1.48@7286.7,3361.59
PE2: J2.1 U3.1 | length 3134.6
  Top Layer w6: U3.1@6197.15,4285.83 6328.9,4285.83 6356.99,4257.74 6356.99,3972.74 6390.99,3938.74 6833.41,3938.74 7252.99,4358.32 7252.99,5311.74 7329.99,5388.74 7329.99,5564.74 7350.01,5584.75 7424.01,5584.75 7455.99,5616.74 7455.99,5751.74 7446.14,5761.59 J2.1@7386.7,5761.59
PE3: J2.2 U3.2 | length 2915.4
  Top Layer w6: U3.2@6197.15,4305.52 6341.21,4305.52 6368.99,4277.74 6368.99,3989.74 6407.99,3950.74 6828.44,3950.74 7240.99,4363.29 7240.99,5514.77 7322.98,5596.75 7368.01,5596.75 7386.7,5615.44 J2.2@7386.7,5661.59
PE4: J2.3 U3.3 | length 2978.7
  Top Layer w6: U3.3@6197.15,4325.2 6350.53,4325.2 6380.99,4294.74 6380.99,4004.74 6422.99,3962.74 6823.47,3962.74 7228.99,4368.26 7228.99,5519.74 7336.99,5627.74 7336.99,5711.29 J2.3@7286.7,5761.59
PE5: J2.4 U3.4 | length 2860.6
  Top Layer w6: U3.4@6197.15,4344.89 6357.84,4344.89 6392.99,4309.74 6392.99,4019.74 6437.99,3974.74 6818.5,3974.74 7138.99,4295.23 7138.99,5518.97 7173.76,5553.74 7233.99,5553.74 7286.7,5606.44 J2.4@7286.7,5661.59
PE6: J2.5 U3.5 | length 2940.3
  Top Layer w6: U3.5@6197.15,4364.57 6361.16,4364.57 6404.99,4320.74 6404.99,4032.74 6450.99,3986.74 6813.53,3986.74 7126.99,4300.2 7126.99,5523.94 7168.79,5565.74 7215.99,5565.74 7236.99,5586.74 7236.99,5711.29 J2.5@7186.7,5761.59
PE7: J2.38 U3.38 | length 961.1
  Top Layer w6: J2.38@5587.12,5662.02 5587.12,5591.66 5685.99,5492.79 5685.99,5434.74 5892.03,5228.7 U3.38@5892.03,4827.17
PE8: J2.39 U3.39 | length 1094.4
  Top Layer w6: J2.39@5487.12,5762.02 5535.62,5713.51 5535.62,5626.19 5673.99,5487.82 5673.99,5429.77 5872.35,5231.42 U3.39@5872.35,4827.17
PE9: J2.40 U3.40 | length 1030.2
  Top Layer w6: J2.40@5487.12,5662.02 5487.12,5612.61 5585.99,5513.74 5585.99,5420.74 5617.99,5388.74 5692.99,5388.74 5852.66,5229.07 U3.40@5852.66,4827.17
PE10: J2.41 U3.41 | length 1338.4
  Top Layer w6: J2.41@5387.12,5762.02 5437.99,5711.14 5437.99,5607.74 5380.99,5550.74 5380.99,5390.74 5450.99,5320.74 5744.02,5320.74 5832.98,5231.79 U3.41@5832.98,4827.17
PE11: J2.42 U3.42 | length 1198
  Top Layer w6: J2.42@5387.12,5662.02 5387.12,5614.74 5368.99,5596.61 5368.99,5385.77 5446.02,5308.74 5739.05,5308.74 5813.29,5234.5 U3.42@5813.29,4827.17
PE12: J2.43 U3.43 | length 1316.3
  Top Layer w6: J2.43@5287.12,5762.02 5341.99,5707.14 5341.99,5395.8 5441.05,5296.74 5734.08,5296.74 5793.6,5237.21 U3.43@5793.61,4827.17
PE13: J2.44 U3.44 | length 1208.1
  Top Layer w6: J2.44@5287.12,5662.02 5287.12,5433.7 5436.08,5284.74 5729.11,5284.74 5773.92,5239.93 U3.44@5773.92,4827.17
PE14: J2.45 U3.45 | length 1338.4
  Top Layer w6: J2.45@5187.12,5762.02 5238.99,5710.14 5238.99,5464.86 5431.11,5272.74 5718.99,5272.74 5754.23,5237.5 U3.45@5754.23,4827.17
PE15: J2.46 U3.46 | length 1223.8
  Top Layer w6: J2.46@5187.12,5662.02 5187.12,5499.76 5426.14,5260.74 5702.99,5260.74 5734.55,5229.18 U3.46@5734.55,4827.17
SPIM_IO0: JP8.7 U4.5 | length 853.8
  Top Layer w6: JP8.7@4763.99,4443.74 4813.99,4493.74 4813.99,4689.74 4835.99,4711.74 5003.93,4711.74 5203.25,4911.06 U4.5@5309.37,4911.06
SPIM_IO1: JP8.10 U4.2 | length 1153.4
  Top Layer w6: JP8.10@4763.99,4343.74 4705.99,4343.74 4687.99,4361.74 4687.99,4722.74 4722.99,4757.74 4992.99,4757.74 5115.37,4880.12 5115.37,4993.06 5097.37,5011.06 U4.2@5019.37,5011.06
SPIM_IO2: JP8.13 U4.3 | length 1202.2
  Top Layer w6: JP8.13@4763.99,4243.74 4699.99,4243.74 4675.99,4267.74 4675.99,4727.71 4718.02,4769.74 4988.02,4769.74 5103.37,4885.09 5103.37,4947.06 5089.37,4961.06 U4.3@5019.37,4961.06
SPIM_IO3: JP8.16 U4.7 | length 1393.4
  Top Layer w6: JP8.16@4763.99,4143.74 4663.99,4243.74 4663.99,4736.74 4709.99,4782.74 4957.99,4782.74 v1(4979.99,4804.74) ; v1(5186.31,5011.06) U4.7@5309.37,5011.06
  Bottom Layer w6: v1(4979.99,4804.74) v1(5186.31,5011.06)
SPIM_NSS: JP8.4 R11.1 U4.1 | length 1201.3
  Top Layer w6: JP8.4@4763.99,4543.74 4716.99,4543.74 4699.99,4560.74 4699.99,4711.74 4727.99,4739.74 4997.99,4739.74 5130.37,4872.12 5130.37,5038.06 5107.37,5061.06 U4.1@5019.37,5061.06 4978.37,5061.06 4970.37,5069.06 4970.37,5135.06 4980.26,5144.94 R11.1@5043.95,5144.94
SPIM_SCK: JP8.1 R12.1 U4.6 | length 819.8
  Top Layer w6: JP8.1@4763.99,4643.74 4763.99,4701.74 4789.99,4727.74 5002.96,4727.74 5236.28,4961.06 U4.6@5309.37,4961.06 R12.1@5418.37,4961.06
SWO: CN2.6 CN7.6 R15.1 R42.1 | length 2427.9
  Top Layer w6: v1(3136.16,4024.06) R42.1@3136.16,4085.02 ; v1(3174.37,3813.06) 3174.37,3442.06 3412.37,3204.06 3412.37,3112.86 CN7.6@3361.85,3062.34 ; v1(4039.14,3720.82) 4039.14,3746.82 4071.37,3779.06 4196.31,3779.06 CN2.6@4247.99,3830.74
  Bottom Layer w6: v1(3136.16,4024.06) 3136.16,3851.26 v1(3174.37,3813.06) 3241.37,3746.06 3644.37,3746.06 3669.6,3720.82 v1(4039.14,3720.82) ; CN2.6@4247.99,3830.74 4248.68,3830.06 R15.1@4344.99,3830.06
USB_M: CN1.2 R22.1 TP2.2 | length 897.3
  Top Layer w6: R22.1@7297.03,3952.54 7327.79,3952.54 v1(7358.99,3983.74) 7376.4,4001.15 CN1.2@7553.06,4001.15
  Bottom Layer w6: v1(7358.99,3983.74) 7358.99,3959.27 7550.99,3767.27 7550.99,3558.74 7578.99,3530.74 TP2.2@7655.99,3530.74
USB_P: CN1.3 R20.1 TP2.3 | length 832.9
  Top Layer w6: R20.1@7296.99,4026.74 7325.99,4026.74 ; 7326.2,4026.94 7325.99,4026.74 ; CN1.3@7553.06,4026.74 v1(7352.99,4026.74) 7325.99,4026.74
  Bottom Layer w6: v1(7352.99,4026.74) 7377.99,4026.74 7391.99,4012.74 7391.99,3943.24 7562.99,3772.24 7562.99,3654.74 7586.99,3630.74 TP2.3@7655.99,3630.74
USBM: CN6.2 R38.1 TP3.2 | length 708.8
  Top Layer w6: v1(3364.43,5710.34) 3389.21,5710.34 ; R38.1@3388.7,5612.34 3389.21,5612.86 3389.21,5710.34 ; CN6.2@3389.21,5813.91 3389.21,5710.34
  Bottom Layer w6: v1(3364.43,5710.34) 3585.43,5710.34 3611.43,5684.34 3611.43,5532.34 3593.43,5514.34 TP3.2@3546.43,5514.34
USBP: CN6.3 R37.1 TP3.3 | length 904.2
  Top Layer w6: R37.1@3314.85,5611.23 v1(3314.85,5710.34) 3363.62,5759.12 CN6.3@3363.62,5813.91
  Bottom Layer w6: v1(3314.85,5710.34) 3336.85,5732.34 3590.43,5732.34 3624.43,5698.34 3624.43,5437.34 3601.43,5414.34 ; TP3.3@3546.43,5412.27 3601.43,5412.27
VBAT: CB4.1 J2.6 R4.1 U3.6 | length 2761.5
  Top Layer w10: U3.6@6197.15,4384.26 6382.47,4384.26 6420.99,4345.74 6420.99,4129.74 6453.99,4096.74 CB4.1@6513.99,4096.74 6513.99,4062.24 ; R4.1@6513.99,4027.74 6513.99,4062.24 ; J2.6@7186.7,5661.59 7186.7,5616.44 7145.99,5575.74 7070.99,5575.74 7033.99,5538.74 7033.99,4227 6869.23,4062.24 6513.99,4062.24
VBUS: CN1.1 D1.1 TP2.1 | length 748.7
  Top Layer w20: 7513.37,3972.06 7470.31,3972.06 7443.99,3945.74 7443.99,3845.74 7525.99,3763.74 D1.1@7525.99,3711.74 7574.99,3711.74 7592.73,3694 v1(7592.73,3431.06)
  Bottom Layer w20: v1(7592.73,3431.06) 7655.68,3431.06 TP2.1@7655.99,3430.74
VCC: C8.2 C9.2 C10.2 C11.2 C12.2 C14.1 J9.1 P1.1 R43.2 RP1.5 RP1.6 RP1.7 RP1.8 U6.1 U6.9 U6.24 U6.36 U6.48 U7.5 | length 3035.7
  Top Layer w10: U6.24@3171,4392.75 3250.78,4392.75 v1(3269.37,4411.34) ; v1(3283.85,4608.34) 3289.11,4613.6 U6.9@3289.11,4668.54 ; v1@3446.59,4274.14 U6.36@3446.59,4333.69 ; U6.1@3446.59,4668.34 3446.59,4628.08 3429.85,4611.34 v1(3429.85,4601.34) 3458.85,4601.34 3466.79,4609.29 U6.48@3505.64,4609.29
  Top Layer w20: U7.5@3610.85,5369.16 3610.85,5224.44 C14.1@3610.47,5224.06 3646.36,5224.06 3660.85,5209.58 3660.85,4833.34 3635.85,4808.34 J9.1@3635.85,4689.34
  Bottom Layer w20: C12.2@3253.85,4555.34 3253.85,4609.34 ; v1(3269.37,4411.34) C10.2@3323.37,4411.34 3323.37,4328.82 3378.23,4273.95 v1(3446.77,4273.95) C11.2@3498.3,4273.95 ; v1(3283.85,4608.34) 3282.85,4609.34 3253.85,4609.34 ; v1(3429.85,4601.34) 3413.85,4601.34 3400.85,4588.34 C8.2@3400.85,4555.34 C9.2@3474.85,4555.34 ; RP1.8@3455.94,5183.06 RP1.7@3491.37,5183.06 RP1.6@3526.8,5183.06 RP1.5@3562.23,5183.06 v1(3661.37,5183.06) ; C11.2@3498.43,4274.08 3498.43,4237.84 3515.93,4220.34 P1.1@3604.85,4220.34 3604.85,4291.34 3576.85,4319.34 3576.85,4521.34 3542.85,4555.34 C9.2@3474.85,4555.34 ; J9.1@3635.85,4689.34 3474.85,4689.34 ; 3253.85,4609.34 3253.85,4659.34 3283.85,4689.34 3474.85,4689.34 ; C9.2@3474.85,4555.34 3474.85,4689.34
VCC3.5V: C17.1 D5.1 R50.2 U5.5 | length 231.2
  Top Layer w20: U5.5@3241.64,5369.23 3241.64,5139.12 D5.1@3242.43,5138.34
VDD: B2.1 CB10.1 CB11.1 CB12.1 CB13.1 CB14.1 CT3.1 J1.25 J1.50 J2.11 J2.28 J2.50 JP1.1 JP3.2 JP4.1 L3.1 R4.2 R13.1 U3.11 U3.28 U3.50 U3.75 U3.100 | length 14349.9
  Top Layer w10: 5487.12,5844.87 5487.99,5845.74 ; U3.75@5586.91,4285.83 5664.09,4285.83 v1(5681.99,4303.74) ; U3.50@5655.81,4827.17 5655.81,4751.92 v1(5670.99,4736.74) ; v1(6046.99,4749.74) 6067.79,4749.74 6088.88,4770.83 U3.28@6088.88,4827.17 ; J2.28@6086.7,5661.59 J2.28@6087.12,5662.02 6136.99,5711.89 6136.99,5845.74 ; v1(6111.99,4505.74) 6135.05,4482.69 U3.11@6206.99,4482.69 ; v1(6113.99,4340.94) 6128.25,4326.69 U3.100@6128.25,4216.94 ; R4.2@6576.93,4027.71 6630.89,4027.71 v3(6630.99,4027.82)
  Top Layer w20: JP4.1@4339.37,4895.06 JP1.1@4469.37,4895.06 4469.37,4797.36 4514.99,4751.74 JP3.2@4514.99,4700.76 4459.02,4700.76 4421.98,4663.73 R13.1@4369.3,4663.73 ; v1(4930.99,4038.74) 5055.99,3913.74 5055.99,3548.68 5006.05,3498.74 B2.1@4777.99,3498.74 B2.1@4777.99,3139.74 4843.99,3139.74 4893.99,3189.74 6185.99,3189.74 ; 4937.99,5843.74 4898.99,5804.74 4898.99,5700.74 4937.72,5662.02 J2.50@4987.12,5662.02 4987.12,5377.87 v1(4985.99,5376.74) 5233.99,5376.74 5395.99,5214.74 5508.37,5214.74 5560.37,5162.74 v1(5560.37,4982.06) ; 4939.99,5845.74 5487.99,5845.74 6136.99,5845.74 6856.99,5845.74 6886.7,5816.04 J2.11@6886.7,5761.59 ; J1.25@6187.12,3262.02 6187.12,3190.87 6185.99,3189.74 ; v3(6447.99,5039.74) 6504.94,5039.74 L3.1@6505.53,5039.15 ; J1.50@7386.7,3361.59 7445.14,3361.59 7470.99,3335.74 7470.99,3219.74 7440.99,3189.74 6185.99,3189.74
  Bottom Layer w20: JP3.2@4514.99,4700.76 4620.99,4700.76 ; v1(4930.99,4038.74) 4682.73,4038.74 4620.99,4100.48 4620.99,4700.76 ; v1(4985.99,5376.74) 4680.99,5376.74 4620.99,5316.74 4620.99,4700.76 ; v1(5560.37,4982.06) 5560.37,4834.06 5540.37,4814.06 5540.37,4702.93 5557.56,4685.74 5587.18,4685.74 CT3.1@5587.33,4685.89 5625.84,4685.89 5625.99,4685.74 CB12.1@5670.99,4685.74 ; v1(5670.99,4736.74) CB12.1@5670.99,4685.74 ; v1(5681.99,4303.74) CB11.1@5729.2,4303.7 ; CB11.1@5729.2,4303.7 5774.95,4303.7 5795.99,4324.74 5795.99,4640.74 5796.99,4641.74 ; CB14.1@6062.03,4505.94 CB10.1@6062.03,4340.94 v1(6113.99,4340.94) 6336.79,4340.94 6384.99,4292.74 6384.99,4082.74 6439.91,4027.82 v3(6630.99,4027.82) ; v1(6111.99,4505.74) 6111.79,4505.94 CB14.1@6062.03,4505.94 6062.03,4613.7 6033.99,4641.74 5982.99,4641.74 ; v3(6447.99,5039.74) 6093.99,5039.74 6046.99,4992.74 v1(6046.99,4749.74) CB13.1@6046.99,4704.74 5999.99,4704.74 5982.99,4687.74 5982.99,4641.74 ; CB12.1@5670.99,4685.74 5670.99,4657.74 5686.99,4641.74 5796.99,4641.74 ; 5796.99,4641.74 5982.99,4641.74
VDDA: CB8.2 CB9.2 L3.2 R17.1 U3.22 | length 701.8
  Top Layer w10: U3.22@6197.15,4699.22 6337.47,4699.22 6542.16,4903.91 CB8.2@6588.37,4903.91
  Top Layer w30: L3.2@6505.53,4978.15 6588.12,4978.15 CB9.2@6588.37,4977.91 ; CB8.2@6588.37,4903.91 CB9.2@6588.37,4977.91 ; R17.1@6588.37,5046.74 CB9.2@6588.37,4977.91
VIN: CN4.1 CT1.1 J4.8 TP1.1 U1.3 | length 4795.5
  Top Layer w20: U1.3@4720.84,3629.93 4827.24,3629.93 4840.37,3643.06 CT1.1@4840.37,3679.06 4906.99,3679.06 4927.99,3700.06 v1(4927.99,3738.06) 4927.99,3851.74 v1(4813.99,3965.74)
  Bottom Layer w20: TP1.1@4660.99,5459.74 CN4.1@4384.99,5459.74 4384.99,5362.74 4196.99,5174.74 4196.99,4217.86 4449.12,3965.74 v1(4813.99,3965.74) ; v1@4928.37,3738.74 6639.99,3738.74 6686.69,3692.04 J4.8@6686.69,3561.59
VREF: CB6.1 CB7.1 L1.2 U3.21 | length 843.7
  Top Layer w10: U3.21@6197.15,4679.54 6355.79,4679.54 6432.2,4755.94 CB7.1@6587.95,4755.94
  Top Layer w30: v2(6522.99,4828.74) 6523.57,4829.31 CB6.1@6587.29,4829.31 6587.29,4756.61 CB7.1@6587.95,4755.94 ; v2(6731.99,4829.74) 6732.53,4830.28 L1.2@6732.53,4903.15
  Bottom Layer w30: v2(6522.99,4828.74) 6523.99,4829.74 v2(6731.99,4829.74)
VSSA: CB6.2 CB7.2 CB8.1 CB9.1 L2.2 U3.19 U3.20 | length 994.8
  Top Layer w10: U3.19@6197.15,4640.17 6377.99,4640.17 ; U3.20@6206.99,4659.85 6377.99,4659.85
  Top Layer w30: 6377.99,4649.74 6397.99,4649.74 6453.99,4705.74 6633.99,4705.74 6648.95,4720.7 CB7.2@6648.95,4755.94 ; CB9.1@6649.37,4977.91 6648.95,4977.49 6648.95,4829.31 CB6.2@6648.29,4829.31 6648.29,4756.61 CB7.2@6648.95,4755.94 ; L2.2@6733.03,4755.54 6732.62,4755.94 CB7.2@6648.95,4755.94
"": CN1.4 CN1.MH1 CN1.MH2 CN3.11 CN3.17 CN3.19 CN6.4 CN6.MH1 CN6.MH2 J1.23 J2.12 J2.13 J2.19 J2.20 J2.22 J4.1 U3.73 U6.2 U6.3 U6.4 U6.5 U6.6 U6.14 U6.15 U6.16 U6.17 U6.18 U6.21 U6.22 U6.29 U6.38 U6.41 U6.42 U6.43 U6.45 U6.46 Y2.2 Y2.4

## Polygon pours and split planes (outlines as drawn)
GND on Top Layer (solid, remove dead copper, pour order 0): 3664.37,6008.06 3712.37,5960.06 3712.37,3804.57 3804.85,3804.57 3806.37,3803.06 3806.37,5682.06 3809.37,5685.06 4072.37,5685.06 4072.37,5969.06 7522.37,5969.06 7522.37,5804.06 7709.37,5804.06 7711.37,5802.06 7711.37,3237.06 7536.37,3237.06 7536.37,3056.06 4031.37,3056.06 4026.37,3061.06 4026.37,3287.06 4020.37,3293.06 3809.37,3293.06 3809.37,3529.06 3811.37,3531.06 3716.72,3531.06 3715.37,3529.71 3715.37,3054.06 3674.37,3013.06 3069.37,3013.06 3016.37,3066.06 3016.37,5964.06 3060.37,6008.06
GND on Bottom Layer (solid, remove dead copper, pour order 1): 3016.37,6009.06 3663.37,6009.06 3712.37,5960.06 3712.37,3804.06 3806.37,3804.06 3806.37,5682.06 3809.37,5685.06 4071.37,5685.06 4072.37,5686.06 4072.37,5969.2 7521.37,5969.21 7521.37,5805.06 7522.37,5804.06 7709.37,5804.06 7711.37,5802.06 7711.37,3237.06 7536.37,3237.05 7536.37,3056.06 4029.37,3056.06 4025.37,3060.06 4025.37,3288.06 4021.37,3292.06 3809.37,3292.06 3807.37,3294.06 3807.37,3530.06 3805.37,3532.06 3718.71,3532.06 3714.71,3528.06 3714.71,3053.4 3674.37,3013.06 3069.37,3013.06 3016.37,3066.06

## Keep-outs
Top Layer:
  region net "": 3367.85,4333.69 3367.85,4249.34 3357.85,4239.34 3357.85,4196.34 3387.53,4226.03 3387.53,4333.69
  region net "": 3333.43,5263.34 3333.43,5728.92 3363.62,5759.12 3390.43,5759.12 3390.43,5513.92 3366.43,5489.92 3366.43,5263.34
  region net "": 6996.99,3952.54 7327.79,3952.54 7358.99,3983.74 7358.99,4020.74 7352.99,4026.74 7048.99,4026.74 6996.99,3974.74
Bottom Layer:
  region net "": 3357.85,4196.34 3311.14,4196.34 3162.85,4344.63 3162.85,5056.34 3206.85,5100.34 3223.63,5083.56 3174.85,5034.34 3174.85,4365.53 3301.04,4239.34 3357.85,4239.34
  region net "": 4963.99,4443.74 4963.99,4343.74 5062.99,4244.74 5062.99,4344.74
Board Outline Layer:
  circle w8 net "": c7638.38,5898.44 r62.99
  circle w8 net "": c7638.38,3123.76 r62.99
  circle w8 net "": c3891.38,5898.74 r62.99
  circle w8 net "": c3891.37,3124.06 r62.99
  circle w8 net "": c5486.7,5461.59 r62.99
  circle w8 net "": c5436.7,3561.59 r62.99
  circle w8 net "": c7486.7,4861.59 r62.99
  lines w6 net "": 3000,5944 3000.42,3079.3 ; 3000.67,3079.3 ccw(c3079.42,3079.3) 3079.42,3000.56 ; 3000.63,5943.74 cw(c3079.37,5943.74) 3079.37,6022.48 ; 3079.37,6022.59 7073.14,6022.59 7683.84,6022.59 ; 3079.42,3000.6 7073.14,3000.6 7683.35,3000.6 ; 3649.37,3000.6 ccw(c3649.37,3079.34) 3728.11,3079.34 ; 3649.37,6022.74 cw(c3649.37,5944) 3728.11,5944 3728.11,5627.34 ; 3727.68,3601.49 3767.19,3601.49 ; 3727.68,4898.56 3767.19,4898.56 ; 3727.81,3695.09 3767.33,3695.09 ; 3727.81,4822.05 3767.33,4822.05 ; 3728.08,5550.28 3767.6,5550.28 ; 3728.37,3079.6 3728.37,3518.06 3767.37,3518.06 3767.37,3079.54 ccw(c3846.32,3079.54) 3846.32,3000.59 ; 3728.37,3602.34 3728.37,3694.34 ; 3728.37,4821.34 3728.37,3811.06 3767.37,3811.06 3767.37,4821.34 ; 3728.37,4899.34 3728.37,5549.34 ; 3728.94,5626.46 3768.46,5626.46 ; 3767.37,3602.34 3767.37,3694.34 ; 3767.37,4899.34 3767.37,5549.34 ; 3767.63,3079.34 ccw(c3846.37,3079.34) 3846.37,3000.6 ; 3767.63,5627.34 3767.63,5952.55 ; 3767.63,5943.74 cw(c3846.37,5943.74) 3846.37,6022.48 3984.88,6022.48 ; 3767.63,5944 cw(c3846.37,5944) 3846.37,6022.74 ; 7683.95,3000 ccw(c7683.95,3078.74) 7762.69,3078.74 7762.69,5943.7 ; 7683.99,6022.44 cw(c7683.99,5943.7) 7762.73,5943.7

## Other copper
Top Layer:
  drawing of 626 lines, arcs and shapes, not listed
